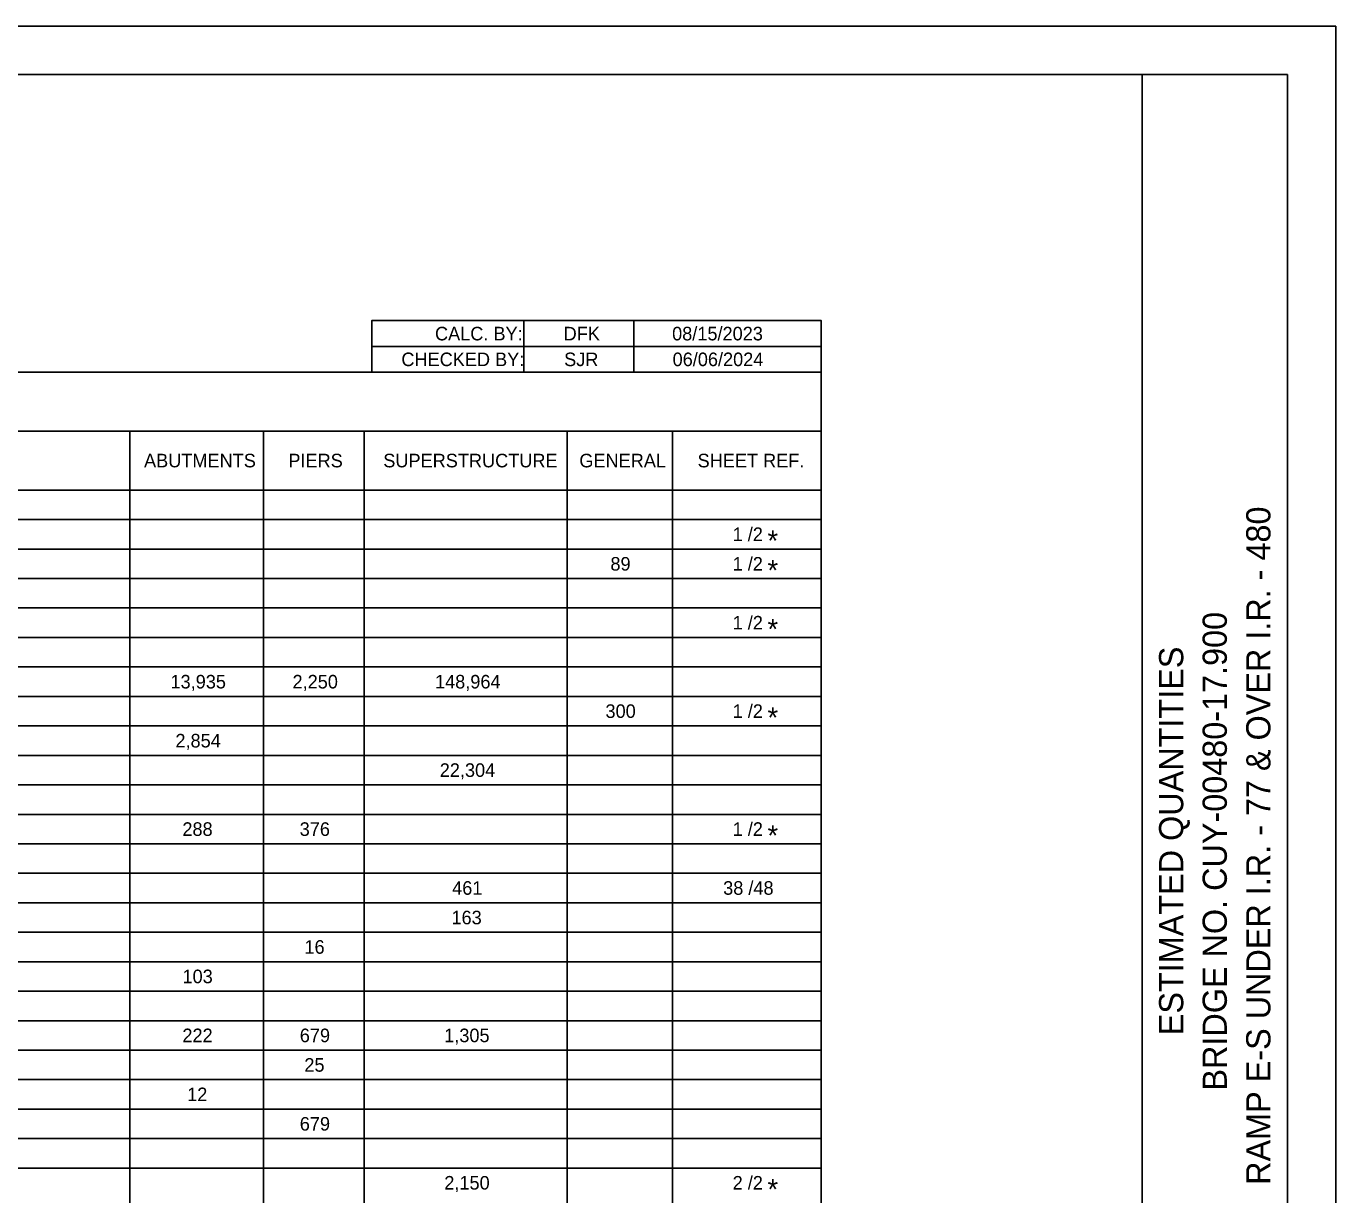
# Model space of a CAD drawing. Extents: x 0 to 34, y 0 to 22.
# Drawn here: x 20.48 to 34, y 9.93 to 22 of the extents above; entities that cross this region are included whole.
import ezdxf

# ---------------------------------------------------------------- set-up
doc = ezdxf.new("R2010")
doc.units = 0
for name, color, linetype in [('SH_Border', 7, 'Continuous'), ('SH_Cut_Line', 7, 'Continuous'), ('SH_Data', 7, 'Continuous'), ('SH_Text', 7, 'Continuous')]:
    doc.layers.add(name, color=color, linetype=linetype)

msp = doc.modelspace()

# ---------------------------------------------------------------- linework, layer by layer
at = {"layer": 'SH_Border'}
msp.add_line((32, 0.5), (32, 21.5), dxfattribs=at)
msp.add_lwpolyline([(1.5, 21.5), (33.5, 21.5), (33.5, 0.5), (1.5, 0.5)], close=True, dxfattribs=at)
at = {"layer": 'SH_Cut_Line'}
msp.add_lwpolyline([(0, 0), (34, 0), (34, 22), (0, 22)], close=True, dxfattribs=at)
at = {"layer": 'SH_Text'}
for p, q in [((25.617, 18.96), (25.617, 18.428)), ((26.753, 18.96), (26.753, 18.428)), ((24.047, 18.694), (28.688, 18.694)), ((5.976, 18.428), (28.688, 18.428)), ((28.688, 18.428), (28.688, 3.515)), ((5.976, 17.819), (28.688, 17.819)), ((21.548, 17.819), (21.548, 3.515)), ((22.931, 17.819), (22.931, 3.515)), ((23.97, 17.819), (23.97, 3.515)), ((26.063, 17.819), (26.063, 3.515)), ((27.153, 17.819), (27.153, 3.515)), ((5.976, 17.21), (28.688, 17.21)), ((5.976, 16.906), (28.688, 16.906)), ((5.976, 16.601), (28.688, 16.601)), ((5.976, 16.297), (28.688, 16.297)), ((5.976, 15.993), (28.688, 15.993)), ((5.976, 15.688), (28.688, 15.688)), ((5.976, 15.384), (28.688, 15.384)), ((5.976, 15.08), (28.688, 15.08)), ((5.976, 14.775), (28.688, 14.775)), ((5.976, 14.471), (28.688, 14.471)), ((5.976, 14.167), (28.688, 14.167)), ((5.976, 13.862), (28.688, 13.862)), ((5.976, 13.558), (28.688, 13.558)), ((5.976, 13.254), (28.688, 13.254)), ((5.976, 12.949), (28.688, 12.949)), ((5.976, 12.645), (28.688, 12.645)), ((5.976, 12.341), (28.688, 12.341)), ((5.976, 12.036), (28.688, 12.036)), ((5.976, 11.732), (28.688, 11.732)), ((5.976, 11.428), (28.688, 11.428)), ((5.976, 11.123), (28.688, 11.123)), ((5.976, 10.819), (28.688, 10.819)), ((5.976, 10.515), (28.688, 10.515)), ((5.976, 10.21), (28.688, 10.21))]:
    msp.add_line(p, q, dxfattribs=at)
msp.add_lwpolyline([(24.047, 18.428), (28.688, 18.428), (28.688, 18.96), (24.047, 18.96)], close=True, dxfattribs=at)

# ---------------------------------------------------------------- texts
at = {"layer": 'SH_Data'}
for s, p in [('RAMP E-S UNDER I.R. - 77 & OVER I.R. - 480', (33.325, 10.037)), ('BRIDGE NO. CUY-00480-17.900', (32.875, 11.01)), ('ESTIMATED QUANTITIES', (32.425, 11.582))]:
    msp.add_text(s, height=0.25, rotation=90, dxfattribs=at).set_placement(p)
at = {"layer": 'SH_Text'}
for s, height, p in [('CALC. BY:', 0.14, (24.7, 18.756)), ('    DFK', 0.14, (25.82, 18.756)), ('    08/15/2023', 0.14, (26.94, 18.756)), ('CHECKED BY:', 0.14, (24.353, 18.49)), ('SJR', 0.14, (26.033, 18.49)), ('06/06/2024', 0.14, (27.153, 18.49)), ('ABUTMENTS', 0.14, (21.696, 17.445)), ('PIERS', 0.14, (23.186, 17.445)), ('SUPERSTRUCTURE', 0.14, (24.166, 17.445)), ('GENERAL', 0.14, (26.19, 17.445)), ('SHEET REF.', 0.14, (27.411, 17.445)), ('1 /2', 0.14, (27.773, 16.684)), ('*', 0.21, (28.133, 16.583)), ('89', 0.14, (26.511, 16.379)), ('1 /2', 0.14, (27.773, 16.379)), ('*', 0.21, (28.133, 16.278)), ('1 /2', 0.14, (27.773, 15.771)), ('*', 0.21, (28.133, 15.67)), ('13,935', 0.14, (21.969, 15.162)), ('2,250', 0.14, (23.229, 15.162)), ('148,964', 0.14, (24.7, 15.162)), ('300', 0.14, (26.46, 14.858)), ('1 /2', 0.14, (27.773, 14.858)), ('*', 0.21, (28.133, 14.757)), ('2,854', 0.14, (22.02, 14.553)), ('22,304', 0.14, (24.749, 14.249)), ('288', 0.14, (22.092, 13.64)), ('376', 0.14, (23.303, 13.64)), ('1 /2', 0.14, (27.773, 13.64)), ('*', 0.21, (28.133, 13.539)), ('461', 0.14, (24.877, 13.032)), ('38 /48', 0.14, (27.675, 13.032)), ('163', 0.14, (24.87, 12.727)), ('16', 0.14, (23.352, 12.423)), ('103', 0.14, (22.093, 12.119)), ('222', 0.14, (22.092, 11.51)), ('679', 0.14, (23.304, 11.51)), ('1,305', 0.14, (24.795, 11.51)), ('25', 0.14, (23.351, 11.205)), ('12', 0.14, (22.141, 10.901)), ('679', 0.14, (23.304, 10.597)), ('2,150', 0.14, (24.796, 9.988)), ('2 /2', 0.14, (27.773, 9.988)), ('*', 0.21, (28.133, 9.887))]:
    msp.add_text(s, height=height, dxfattribs=at).set_placement(p)

doc.saveas('drawing.dxf')
